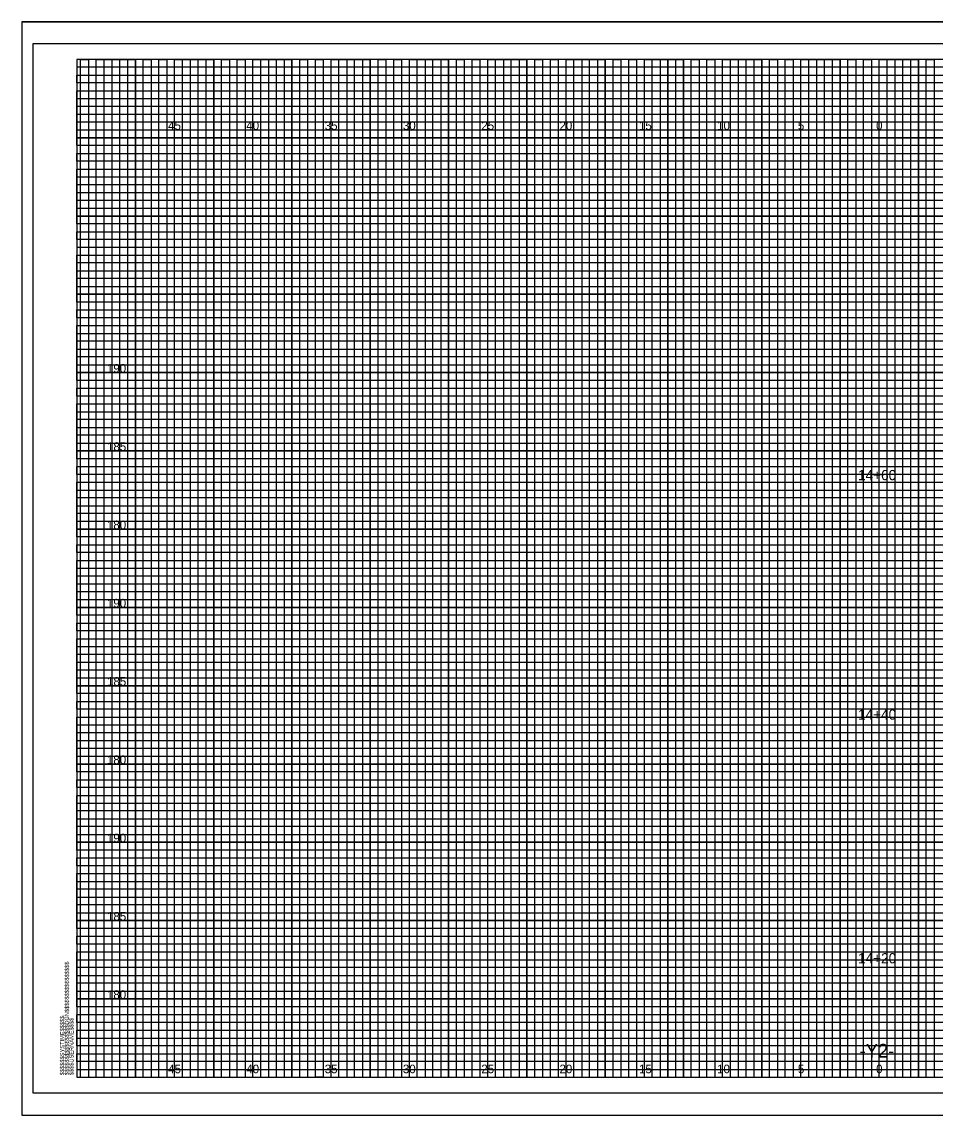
# Model space of a CAD drawing. Extents: x -4 to 103, y -2 to 67.
# Drawn here: x -3.5 to 54.8, y -2.4 to 67.4 of the extents above; entities that cross this region are included whole.
import ezdxf

# ---------------------------------------------------------------- set-up
doc = ezdxf.new("R2010")
doc.units = 0
for name, color, linetype in [('Exist XS Ground Line', 7, 'Continuous'), ('Old_Level_10', 7, 'Continuous'), ('Old_Level_16', 7, 'Continuous'), ('Old_Level_3', 7, 'Continuous'), ('Old_Level_4', 7, 'Continuous'), ('Old_Level_5', 7, 'Continuous'), ('Old_Level_6', 7, 'Continuous'), ('Old_Level_8', 7, 'Continuous'), ('Prop XS Dump Level', 7, 'Continuous'), ('Prop XS Pvmt Edge Slope', 7, 'Continuous'), ('Prop XSC Text', 7, 'Continuous')]:
    doc.layers.add(name, color=color, linetype=linetype)

msp = doc.modelspace()

# ---------------------------------------------------------------- linework, layer by layer
at = {"layer": 'Old_Level_10'}
for p, q in [((1.25, 0), (1.25, 65)), ((3.75, 0), (3.75, 65)), ((6.25, 0), (6.25, 65)), ((8.75, 0), (8.75, 65)), ((11.25, 0), (11.25, 65)), ((13.75, 0), (13.75, 65)), ((16.25, 0), (16.25, 65)), ((18.75, 0), (18.75, 65)), ((21.25, 0), (21.25, 65)), ((23.75, 0), (23.75, 65)), ((26.25, 0), (26.25, 65)), ((28.75, 0), (28.75, 65)), ((31.25, 0), (31.25, 65)), ((33.75, 0), (33.75, 65)), ((36.25, 0), (36.25, 65)), ((38.75, 0), (38.75, 65)), ((41.25, 0), (41.25, 65)), ((43.75, 0), (43.75, 65)), ((46.25, 0), (46.25, 65)), ((48.75, 0), (48.75, 65)), ((51.25, 0), (51.25, 65)), ((53.75, 0), (53.75, 65)), ((0, 62.5), (74.25, 62.5)), ((0, 60), (102.5, 60)), ((0, 57.5), (102.5, 57.5)), ((0, 55), (102.5, 55)), ((0, 52.5), (102.5, 52.5)), ((0, 50), (102.5, 50)), ((0, 47.5), (102.5, 47.5)), ((0, 45), (102.5, 45)), ((0, 42.5), (102.5, 42.5)), ((0, 40), (102.5, 40)), ((0, 37.5), (102.5, 37.5)), ((0, 35), (102.5, 35)), ((0, 32.5), (102.5, 32.5)), ((0, 30), (102.5, 30)), ((0, 27.5), (102.5, 27.5)), ((0, 25), (102.5, 25)), ((0, 22.5), (102.5, 22.5)), ((0, 20), (102.5, 20)), ((0, 17.5), (102.5, 17.5)), ((0, 15), (102.5, 15)), ((0, 12.5), (102.5, 12.5)), ((0, 10), (102.5, 10)), ((0, 7.5), (102.5, 7.5)), ((0, 5), (102.5, 5)), ((0, 2.5), (102.5, 2.5))]:
    msp.add_line(p, q, dxfattribs=at)
at = {"layer": 'Old_Level_3'}
for p, q in [((-3.5, 67.4), (103.4, 67.4)), ((-3.5, 67.4), (-3.5, -2.425)), ((-3.5, -2.425), (103.4, -2.425))]:
    msp.add_line(p, q, dxfattribs=at)
at = {"layer": 'Old_Level_4'}
msp.add_lwpolyline([(103, 66), (-2.8, 66), (-2.8, -1), (103, -1)], close=True, dxfattribs=at)
at = {"layer": 'Old_Level_5'}
msp.add_lwpolyline([(103.4, 67.4), (-3.5, 67.4), (-3.5, -2.425), (103.4, -2.425)], close=True, dxfattribs=at)
at = {"layer": 'Old_Level_6'}
msp.add_lwpolyline([(102.5, 65), (0, 65), (0, 0), (102.5, 0)], close=True, dxfattribs=at)
at = {"layer": 'Old_Level_8'}
for points in [[(1.25, 0), (1.25, 65), (3.75, 65), (3.75, 0), (6.25, 0), (6.25, 65), (8.75, 65), (8.75, 0), (11.25, 0), (11.25, 65), (13.75, 65), (13.75, 0), (16.25, 0), (16.25, 65), (18.75, 65), (18.75, 0), (21.25, 0), (21.25, 65), (23.75, 65), (23.75, 0), (26.25, 0), (26.25, 65), (28.75, 65), (28.75, 0), (31.25, 0), (31.25, 65), (33.75, 65), (33.75, 0), (36.25, 0), (36.25, 65), (38.75, 65), (38.75, 0), (41.25, 0), (41.25, 65), (43.75, 65), (43.75, 0), (46.25, 0), (46.25, 65), (48.75, 65), (48.75, 0), (51.25, 0), (51.25, 65), (53.75, 65), (53.75, 0)], [(102.5, 60), (0, 60), (0, 62.5), (74.25, 62.5)], [(102.5, 55), (0, 55), (0, 57.5), (102.5, 57.5)], [(102.5, 50), (0, 50), (0, 52.5), (102.5, 52.5)], [(102.5, 45), (0, 45), (0, 47.5), (102.5, 47.5)], [(102.5, 40), (0, 40), (0, 42.5), (102.5, 42.5)], [(102.5, 35), (0, 35), (0, 37.5), (102.5, 37.5)], [(102.5, 30), (0, 30), (0, 32.5), (102.5, 32.5)], [(102.5, 25), (0, 25), (0, 27.5), (102.5, 27.5)], [(102.5, 20), (0, 20), (0, 22.5), (102.5, 22.5)], [(102.5, 15), (0, 15), (0, 17.5), (102.5, 17.5)], [(102.5, 10), (0, 10), (0, 12.5), (102.5, 12.5)], [(102.5, 5), (0, 5), (0, 7.5), (102.5, 7.5)], [(0, 2.5), (102.5, 2.5)]]:
    msp.add_lwpolyline(points, dxfattribs=at)
at = {"layer": 'Prop XSC Text'}
for points in [[(0.25, 0), (0.25, 65), (0.75, 65), (0.75, 0), (1.75, 0), (1.75, 65), (2.25, 65), (2.25, 0), (2.75, 0), (2.75, 65), (3.25, 65), (3.25, 0), (4.25, 0), (4.25, 65), (4.75, 65), (4.75, 0), (5.25, 0), (5.25, 65), (5.75, 65), (5.75, 0), (6.75, 0), (6.75, 65), (7.25, 65), (7.25, 0), (7.75, 0), (7.75, 65), (8.25, 65), (8.25, 0), (9.25, 0), (9.25, 65), (9.75, 65), (9.75, 0), (10.25, 0), (10.25, 65), (10.75, 65), (10.75, 0), (11.75, 0), (11.75, 65), (12.25, 65), (12.25, 0), (12.75, 0), (12.75, 65), (13.25, 65), (13.25, 0), (14.25, 0), (14.25, 65), (14.75, 65), (14.75, 0), (15.75, 0), (15.25, 0), (15.25, 65), (15.75, 65), (15.75, 0), (16.75, 0), (16.75, 65), (17.25, 65), (17.25, 0), (17.75, 0), (17.75, 65), (18.25, 65), (18.25, 0), (19.25, 0), (19.25, 65), (19.75, 65), (19.75, 0), (20.25, 0), (20.25, 65), (20.75, 65), (20.75, 0), (21.75, 0), (21.75, 65), (22.25, 65), (22.25, 0), (22.75, 0), (22.75, 65), (23.25, 65), (23.25, 0), (24.25, 0), (24.25, 65), (24.75, 65), (24.75, 0), (25.25, 0), (25.25, 65), (25.75, 65), (25.75, 0), (26.75, 0), (26.75, 65), (27.25, 65), (27.25, 0), (27.75, 0), (27.75, 65), (28.25, 65), (28.25, 0), (29.25, 0), (29.25, 65), (29.75, 65), (29.75, 0), (30.25, 0), (30.25, 65), (30.75, 65), (30.75, 0)], [(30.75, 0), (31.75, 0), (31.75, 65), (32.25, 65), (32.25, 0), (32.75, 0), (32.75, 65), (33.25, 65), (33.25, 0), (34.25, 0), (34.25, 65), (34.75, 65), (34.75, 0), (35.25, 0), (35.25, 65), (35.75, 65), (35.75, 0), (36.75, 0), (36.75, 65), (37.25, 65), (37.25, 0), (37.75, 0), (37.75, 65), (37.75, 0)], [(38.25, 65), (38.25, 0), (39.25, 0), (39.25, 65), (39.75, 65), (39.75, 0), (40.25, 0), (40.25, 65), (40.75, 65), (40.75, 0), (41.75, 0), (41.75, 65), (42.25, 65), (42.25, 0), (42.75, 0), (42.75, 65), (43.25, 65), (43.25, 0), (43.75, 0), (44.25, 0), (44.25, 65), (44.75, 65), (44.75, 0), (45.25, 0), (45.25, 65), (45.75, 65), (45.75, 0), (46.75, 0), (46.75, 65), (47.25, 65), (47.25, 0), (47.75, 0), (47.75, 65), (48.25, 65), (48.25, 0), (49.25, 0), (49.25, 65), (49.75, 65), (49.75, 0), (50.25, 0), (50.25, 65), (50.75, 65), (50.75, 0), (51.75, 0), (51.75, 65), (52.25, 65), (52.25, 0), (52.75, 0), (52.75, 65), (53.25, 65), (53.25, 0), (54.25, 0), (54.25, 65), (54.75, 65), (54.75, 0), (55.25, 0)], [(0, 62), (0, 63), (74.25, 63), (74.25, 63.5), (0, 63.5), (0, 64), (74.25, 64), (74.25, 64.5), (0, 64.5)], [(102.5, 62), (0, 62)], [(102.5, 61), (0, 61), (0, 61.5), (102.5, 61.5)], [(102.5, 59.5), (0, 59.5), (0, 60.5), (102.5, 60.5)], [(102.5, 58.5), (0, 58.5), (0, 59), (102.5, 59)], [(102.5, 57), (0, 57), (0, 58), (102.5, 58)], [(102.5, 56), (0, 56), (0, 56.5), (102.5, 56.5)], [(102.5, 54.5), (0, 54.5), (0, 55.5), (102.5, 55.5)], [(102.5, 53.5), (0, 53.5), (0, 54), (102.5, 54)], [(0, 53), (102.5, 53)], [(102.5, 52), (0, 52)], [(102.5, 51), (0, 51), (0, 51.5), (102.5, 51.5)], [(102.5, 49.5), (0, 49.5), (0, 50.5), (102.5, 50.5)], [(102.5, 48.5), (0, 48.5), (0, 49), (102.5, 49)], [(102.5, 47), (0, 47), (0, 48), (102.5, 48)], [(102.5, 46), (0, 46), (0, 46.5), (102.5, 46.5)], [(102.5, 44.5), (0, 44.5), (0, 45.5), (102.5, 45.5)], [(102.5, 43.5), (0, 43.5), (0, 44), (102.5, 44)], [(102.5, 42), (0, 42), (0, 43), (102.5, 43)], [(102.5, 41), (0, 41), (0, 41.5), (102.5, 41.5)], [(102.5, 39.5), (0, 39.5), (0, 40.5), (102.5, 40.5)], [(102.5, 38.5), (0, 38.5), (0, 39), (102.5, 39)], [(102.5, 37), (0, 37), (0, 38), (102.5, 38)], [(102.5, 36), (0, 36), (0, 36.5), (102.5, 36.5)], [(102.5, 34.5), (0, 34.5), (0, 35.5), (102.5, 35.5)], [(102.5, 33.5), (0, 33.5), (0, 34), (102.5, 34)], [(102.5, 32), (0, 32), (0, 33), (102.5, 33)], [(102.5, 31), (0, 31), (0, 31.5)], [(0, 31.5), (102.5, 31.5)], [(102.5, 29.5), (0, 29.5), (0, 30.5), (102.5, 30.5)], [(102.5, 28.5), (0, 28.5), (0, 29), (102.5, 29)], [(102.5, 27), (0, 27), (0, 28), (102.5, 28)], [(102.5, 26), (0, 26), (0, 26.5), (102.5, 26.5)], [(102.5, 24.5), (0, 24.5), (0, 25.5), (102.5, 25.5)], [(102.5, 23.5), (0, 23.5), (0, 24), (102.5, 24)], [(102.5, 22), (0, 22), (0, 23), (102.5, 23)], [(102.5, 21), (0, 21), (0, 21.5), (102.5, 21.5)], [(102.5, 19.5), (0, 19.5), (0, 20.5), (102.5, 20.5)], [(102.5, 18.5), (0, 18.5), (0, 19), (102.5, 19)], [(102.5, 17), (0, 17), (0, 18), (102.5, 18)], [(102.5, 16), (0, 16), (0, 16.5), (102.5, 16.5)], [(102.5, 14.5), (0, 14.5), (0, 15.5), (102.5, 15.5)], [(102.5, 13.5), (0, 13.5), (0, 14), (102.5, 14)], [(102.5, 12), (0, 12), (0, 13), (102.5, 13)], [(102.5, 11), (0, 11), (0, 11.5), (102.5, 11.5)], [(102.5, 9.5), (0, 9.5), (0, 10.5), (102.5, 10.5)], [(102.5, 8.5), (0, 8.5), (0, 9), (102.5, 9)], [(102.5, 7), (0, 7), (0, 8), (102.5, 8)], [(102.5, 6), (0, 6), (0, 6.5), (102.5, 6.5)], [(102.5, 4.5), (0, 4.5), (0, 5.5), (102.5, 5.5)], [(102.5, 3.5), (0, 3.5), (0, 4), (102.5, 4)], [(102.5, 2), (0, 2), (0, 3), (102.5, 3)], [(102.5, 1), (0, 1), (0, 1.5), (102.5, 1.5)], [(0, 0.5), (102.5, 0.5)]]:
    msp.add_lwpolyline(points, dxfattribs=at)

# ---------------------------------------------------------------- texts
at = {"layer": 'Exist XS Ground Line'}
msp.add_text('-Y2-', height=0.875, dxfattribs=at).set_placement((49.998, 1.25))
at = {"layer": 'Old_Level_16'}
for s, p in [('45', (5.84, 60.5)), ('40', (10.831, 60.5)), ('35', (15.84, 60.5)), ('30', (20.831, 60.5)), ('25', (25.84, 60.5)), ('20', (30.831, 60.5)), ('15', (35.906, 60.5)), ('10', (40.897, 60.5)), ('5', (46.057, 60.5)), ('0', (51.049, 60.5)), ('0', (51.049, 60.5)), ('45', (5.84, 0.25)), ('40', (10.831, 0.25)), ('35', (15.84, 0.25)), ('30', (20.831, 0.25)), ('25', (25.84, 0.25)), ('20', (30.831, 0.25)), ('15', (35.906, 0.25)), ('10', (40.897, 0.25)), ('5', (46.057, 0.25)), ('0', (51.049, 0.25)), ('0', (51.049, 0.25))]:
    msp.add_text(s, height=0.55, dxfattribs=at).set_placement(p)
at = {"layer": 'Old_Level_6'}
for s, p in [('$$$$$$$$$$$$$$$$DGN$$$$$$$$$$$$$$$$', (-0.5, 0.125)), ('$$$$$$SYSTIME$$$$$', (-0.797, 0.125)), ('$$$$USERNAME$$$$', (-0.2, 0.125))]:
    msp.add_text(s, height=0.2625, rotation=90, dxfattribs=at).set_placement(p)
at = {"layer": 'Old_Level_8'}
msp.add_text('040397', height=0.0025, rotation=90, dxfattribs=at).set_placement((-0.001, 64.986))
at = {"layer": 'Prop XS Dump Level'}
for s, p in [('190', (1.93, 45)), ('185', (1.938, 40)), ('180', (1.93, 35)), ('190', (1.93, 30)), ('185', (1.938, 25)), ('180', (1.93, 20)), ('190', (1.93, 15)), ('185', (1.938, 10)), ('180', (1.93, 5))]:
    msp.add_text(s, height=0.55, dxfattribs=at).set_placement(p)
at = {"layer": 'Prop XS Pvmt Edge Slope'}
for s, p in [('14+60', (49.893, 38.129)), ('14+40', (49.893, 22.835)), ('14+20', (49.893, 7.27))]:
    msp.add_text(s, height=0.65, dxfattribs=at).set_placement(p)

doc.saveas('drawing.dxf')
